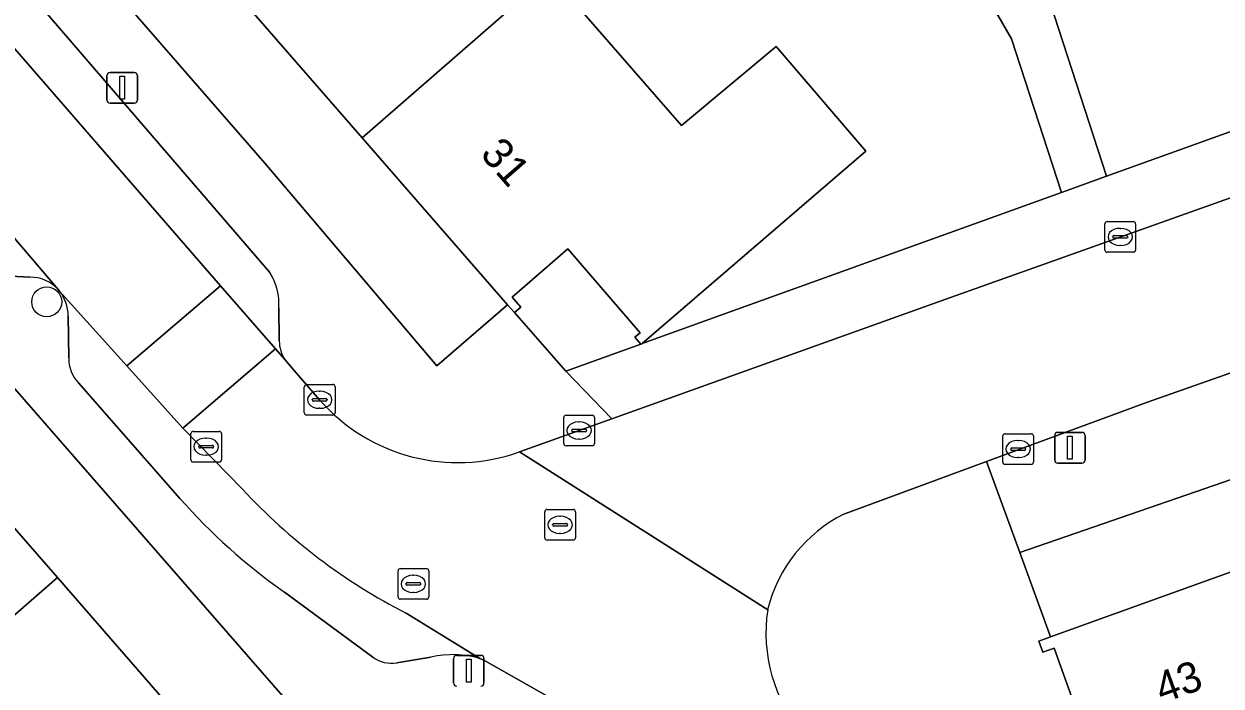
# Model space of a CAD drawing. Extents: x 162523 to 163266, y 381230 to 382050.
# Drawn here: x 162679.21 to 162718.25, y 381760.98 to 381782.56 of the extents above; entities that cross this region are included whole.
import ezdxf

# ---------------------------------------------------------------- set-up
doc = ezdxf.new("R2010")
doc.units = 0
for name, color, linetype in [('IMGEO_Boom', 7, 'Continuous'), ('IMGEO_Erf', 7, 'Continuous'), ('IMGEO_Kolk', 7, 'Continuous'), ('IMGEO_Lichtmast', 7, 'Continuous'), ('IMGEO_Pand', 7, 'Continuous'), ('IMGEO_Pand_nummerreeks', 7, 'Continuous'), ('IMGEO_Parkeervlak_open', 7, 'Continuous'), ('IMGEO_Rijbaan_lokaal_open', 7, 'Continuous'), ('IMGEO_Rioolput', 7, 'Continuous'), ('IMGEO_Voetpad_open', 7, 'Continuous')]:
    doc.layers.add(name, color=color, linetype=linetype)

msp = doc.modelspace()

# ---------------------------------------------------------------- linework, layer by layer
at = {"layer": 'IMGEO_Boom'}
msp.add_circle((162679.951, 381773.503), 0.489, dxfattribs=at)
at = {"layer": 'IMGEO_Erf'}
for points in [[(162646.757, 381824.316), (162687.062, 381778.024), (162692.677, 381771.414), (162694.979, 381773.409), (162690.237, 381778.855), (162685.66, 381784.112), (162681.084, 381789.369), (162676.507, 381794.626), (162671.93, 381799.882), (162667.354, 381805.138), (162662.776, 381810.395), (162658.2, 381815.652), (162653.622, 381820.909), (162648.917, 381826.314)], [(162691.781, 381755.909), (162641.055, 381814.077), (162638.825, 381812.07), (162643.552, 381806.65), (162648.146, 381801.382), (162652.703, 381796.157), (162657.326, 381790.856), (162661.852, 381785.666), (162666.513, 381780.321), (162671.069, 381775.096), (162675.726, 381769.756), (162680.299, 381764.512), (162684.872, 381759.269), (162689.516, 381753.943)], [(162771.368, 381786.733), (162721.003, 381768.545), (162711.69, 381765.328), (162712.683, 381762.58), (162719.702, 381765.1), (162726.218, 381767.44), (162732.846, 381769.821), (162739.192, 381772.1), (162745.775, 381774.464), (162752.294, 381776.805), (162759.028, 381779.223), (162765.611, 381781.587), (162772.373, 381784.016)], [(162699.131, 381772.351), (162699.306, 381772.491), (162696.945, 381775.228), (162695.132, 381773.65), (162695.409, 381773.331), (162695.203, 381773.152), (162696.883, 381771.248), (162699.326, 381772.127)]]:
    msp.add_lwpolyline(points, close=True, dxfattribs=at)
for points in [[(162696.359, 381784.183), (162700.653, 381779.252), (162703.745, 381781.827), (162706.667, 381778.414), (162699.372, 381772.144), (162713.049, 381777.067), (162711.421, 381782.079), (162710.363, 381783.912)], [(162712.395, 381784.129), (162714.518, 381777.596), (162732.297, 381783.996)]]:
    msp.add_lwpolyline(points, dxfattribs=at)
at = {"layer": 'IMGEO_Kolk'}
for p, q in [((162714.538, 381776.119), (162715.39, 381776.119)), ((162714.463, 381775.193), (162714.463, 381776.045)), ((162714.951, 381775.899), (162714.976, 381775.899)), ((162715.464, 381776.045), (162715.464, 381775.193)), ((162714.722, 381775.613), (162714.722, 381775.625)), ((162715.16, 381775.576), (162714.762, 381775.576)), ((162714.765, 381775.662), (162715.163, 381775.662)), ((162714.974, 381775.339), (162714.949, 381775.339)), ((162715.206, 381775.625), (162715.206, 381775.613)), ((162715.39, 381775.119), (162714.538, 381775.119)), ((162688.353, 381769.885), (162688.353, 381770.737)), ((162688.428, 381770.811), (162689.28, 381770.811)), ((162689.354, 381770.737), (162689.354, 381769.885)), ((162688.612, 381770.305), (162688.612, 381770.317)), ((162689.05, 381770.268), (162688.652, 381770.268)), ((162688.655, 381770.354), (162689.053, 381770.354)), ((162688.841, 381770.591), (162688.866, 381770.591)), ((162689.096, 381770.317), (162689.096, 381770.305)), ((162688.864, 381770.031), (162688.839, 381770.031)), ((162689.28, 381769.811), (162688.428, 381769.811)), ((162696.813, 381768.882), (162696.813, 381769.734)), ((162696.888, 381769.808), (162697.74, 381769.808)), ((162697.301, 381769.588), (162697.326, 381769.588)), ((162697.814, 381769.734), (162697.814, 381768.882)), ((162684.652, 381768.355), (162684.652, 381769.207)), ((162684.727, 381769.281), (162685.579, 381769.281)), ((162685.14, 381769.061), (162685.165, 381769.061)), ((162685.653, 381769.207), (162685.653, 381768.355)), ((162697.072, 381769.302), (162697.072, 381769.314)), ((162697.51, 381769.265), (162697.112, 381769.265)), ((162697.115, 381769.351), (162697.513, 381769.351)), ((162697.556, 381769.314), (162697.556, 381769.302)), ((162711.13, 381768.278), (162711.13, 381769.13)), ((162711.205, 381769.204), (162712.057, 381769.204)), ((162712.131, 381769.13), (162712.131, 381768.278)), ((162684.911, 381768.775), (162684.911, 381768.787)), ((162685.349, 381768.738), (162684.951, 381768.738)), ((162684.954, 381768.824), (162685.352, 381768.824)), ((162685.395, 381768.787), (162685.395, 381768.775)), ((162697.74, 381768.808), (162696.888, 381768.808)), ((162697.324, 381769.028), (162697.299, 381769.028)), ((162711.389, 381768.698), (162711.389, 381768.71)), ((162711.432, 381768.747), (162711.83, 381768.747)), ((162711.618, 381768.984), (162711.643, 381768.984)), ((162711.873, 381768.71), (162711.873, 381768.698)), ((162685.579, 381768.281), (162684.727, 381768.281)), ((162685.163, 381768.501), (162685.138, 381768.501)), ((162711.827, 381768.661), (162711.429, 381768.661)), ((162711.641, 381768.424), (162711.616, 381768.424)), ((162712.057, 381768.204), (162711.205, 381768.204))]:
    msp.add_line(p, q, dxfattribs=at)
for points in [[(162714.538, 381776.119), (162715.39, 381776.119)], [(162714.463, 381775.193), (162714.463, 381776.045)], [(162715.464, 381776.045), (162715.464, 381775.193)], [(162715.39, 381775.119), (162714.538, 381775.119)], [(162688.353, 381769.885), (162688.353, 381770.737)], [(162688.428, 381770.811), (162689.28, 381770.811)], [(162689.354, 381770.737), (162689.354, 381769.885)], [(162689.28, 381769.811), (162688.428, 381769.811)], [(162696.813, 381768.882), (162696.813, 381769.734)], [(162696.888, 381769.808), (162697.74, 381769.808)], [(162697.814, 381769.734), (162697.814, 381768.882)], [(162684.652, 381768.355), (162684.652, 381769.207)], [(162684.727, 381769.281), (162685.579, 381769.281)], [(162685.653, 381769.207), (162685.653, 381768.355)], [(162711.13, 381768.278), (162711.13, 381769.13)], [(162711.205, 381769.204), (162712.057, 381769.204)], [(162712.131, 381769.13), (162712.131, 381768.278)], [(162697.74, 381768.808), (162696.888, 381768.808)], [(162685.579, 381768.281), (162684.727, 381768.281)], [(162712.057, 381768.204), (162711.205, 381768.204)]]:
    msp.add_lwpolyline(points, dxfattribs=at)
for centre, radius, start, end in [((162714.54, 381776.043), 0.0765, 91.552, 178.448), ((162714.54, 381776.043), 0.0765, 91.552, 178.448), ((162715.388, 381776.043), 0.0765, 1.552, 88.448), ((162715.388, 381776.043), 0.0765, 1.552, 88.448), ((162714.762, 381775.622), 0.0403, 85.8775, 175.7526), ((162714.759, 381775.612), 0.0366, 178.938, 274.7102), ((162715.163, 381775.619), 0.043, 264.8664, 352.4533), ((162715.167, 381775.624), 0.0386, 1.7309, 96.639), ((162714.54, 381775.195), 0.0765, 181.552, 268.448), ((162714.54, 381775.195), 0.0765, 181.552, 268.448), ((162715.388, 381775.195), 0.0765, 271.552, 358.448), ((162715.388, 381775.195), 0.0765, 271.552, 358.448), ((162688.43, 381770.735), 0.0765, 91.552, 178.448), ((162688.43, 381770.735), 0.0765, 91.552, 178.448), ((162689.278, 381770.735), 0.0765, 1.552, 88.448), ((162689.278, 381770.735), 0.0765, 1.552, 88.448), ((162688.652, 381770.314), 0.0403, 85.8775, 175.7526), ((162688.649, 381770.304), 0.0366, 178.938, 274.7102), ((162689.053, 381770.311), 0.043, 264.8664, 352.4533), ((162689.057, 381770.316), 0.0386, 1.7309, 96.639), ((162688.43, 381769.887), 0.0765, 181.552, 268.448), ((162688.43, 381769.887), 0.0765, 181.552, 268.448), ((162689.278, 381769.887), 0.0765, 271.552, 358.448), ((162689.278, 381769.887), 0.0765, 271.552, 358.448), ((162696.89, 381769.732), 0.0765, 91.552, 178.448), ((162696.89, 381769.732), 0.0765, 91.552, 178.448), ((162697.738, 381769.732), 0.0765, 1.552, 88.448), ((162697.738, 381769.732), 0.0765, 1.552, 88.448), ((162684.729, 381769.205), 0.0765, 91.552, 178.448), ((162684.729, 381769.205), 0.0765, 91.552, 178.448), ((162685.577, 381769.205), 0.0765, 1.552, 88.448), ((162685.577, 381769.205), 0.0765, 1.552, 88.448), ((162697.112, 381769.311), 0.0403, 85.8775, 175.7526), ((162697.109, 381769.301), 0.0366, 178.938, 274.7102), ((162697.513, 381769.308), 0.043, 264.8664, 352.4533), ((162697.517, 381769.313), 0.0386, 1.7309, 96.639), ((162711.207, 381769.128), 0.0765, 91.552, 178.448), ((162711.207, 381769.128), 0.0765, 91.552, 178.448), ((162712.055, 381769.128), 0.0765, 1.552, 88.448), ((162712.055, 381769.128), 0.0765, 1.552, 88.448), ((162684.951, 381768.784), 0.0403, 85.8775, 175.7526), ((162684.948, 381768.774), 0.0366, 178.938, 274.7102), ((162685.352, 381768.781), 0.043, 264.8664, 352.4533), ((162685.356, 381768.786), 0.0386, 1.7309, 96.639), ((162696.89, 381768.884), 0.0765, 181.552, 268.448), ((162696.89, 381768.884), 0.0765, 181.552, 268.448), ((162697.738, 381768.884), 0.0765, 271.552, 358.448), ((162697.738, 381768.884), 0.0765, 271.552, 358.448), ((162711.429, 381768.707), 0.0403, 85.8775, 175.7526), ((162711.426, 381768.697), 0.0366, 178.938, 274.7102), ((162711.83, 381768.704), 0.043, 264.8664, 352.4533), ((162711.834, 381768.709), 0.0386, 1.7309, 96.639), ((162684.729, 381768.357), 0.0765, 181.552, 268.448), ((162684.729, 381768.357), 0.0765, 181.552, 268.448), ((162685.577, 381768.357), 0.0765, 271.552, 358.448), ((162685.577, 381768.357), 0.0765, 271.552, 358.448), ((162711.207, 381768.28), 0.0765, 181.552, 268.448), ((162711.207, 381768.28), 0.0765, 181.552, 268.448), ((162712.055, 381768.28), 0.0765, 271.552, 358.448), ((162712.055, 381768.28), 0.0765, 271.552, 358.448)]:
    msp.add_arc(centre, radius, start, end, dxfattribs=at)
for centre, major_axis, ratio, start_param, end_param in [((162714.95, 381775.619), (-0.387, 0.002), 0.722429, 4.712389, 7.853982), ((162714.975, 381775.619), (-0.39, 0.002), 0.717154, 1.570796, 4.712389), ((162688.84, 381770.311), (-0.387, 0.002), 0.722429, 4.712389, 7.853982), ((162688.865, 381770.311), (-0.39, 0.002), 0.717154, 1.570796, 4.712389), ((162697.3, 381769.308), (-0.387, 0.002), 0.722429, 4.712389, 7.853982), ((162697.325, 381769.308), (-0.39, 0.002), 0.717154, 1.570796, 4.712389), ((162685.139, 381768.781), (-0.387, 0.002), 0.722429, 4.712389, 7.853982), ((162685.164, 381768.781), (-0.39, 0.002), 0.717154, 1.570796, 4.712389), ((162711.617, 381768.704), (-0.387, 0.002), 0.722429, 4.712389, 7.853982), ((162711.642, 381768.704), (-0.39, 0.002), 0.717154, 1.570796, 4.712389)]:
    msp.add_ellipse(centre, major_axis=major_axis, ratio=ratio, start_param=start_param, end_param=end_param, dxfattribs=at)
at = {"layer": 'IMGEO_Lichtmast'}
for p, q in [((162681.917, 381780.081), (162681.917, 381780.881)), ((162681.917, 381780.881), (162681.917, 381780.081)), ((162682.017, 381780.981), (162682.807, 381780.981)), ((162682.807, 381780.981), (162682.017, 381780.981)), ((162682.907, 381780.881), (162682.907, 381780.081)), ((162682.907, 381780.081), (162682.907, 381780.881)), ((162682.807, 381779.981), (162682.017, 381779.981)), ((162682.017, 381779.981), (162682.807, 381779.981)), ((162712.824, 381768.346), (162712.824, 381769.146)), ((162712.824, 381769.146), (162712.824, 381768.346)), ((162712.924, 381769.246), (162713.714, 381769.246)), ((162713.714, 381769.246), (162712.924, 381769.246)), ((162713.814, 381769.146), (162713.814, 381768.346)), ((162713.814, 381768.346), (162713.814, 381769.146)), ((162713.714, 381768.246), (162712.924, 381768.246)), ((162712.924, 381768.246), (162713.714, 381768.246)), ((162693.222, 381761.076), (162693.222, 381761.876)), ((162693.222, 381761.876), (162693.222, 381761.076)), ((162693.322, 381761.976), (162694.112, 381761.976)), ((162694.112, 381761.976), (162693.322, 381761.976)), ((162694.212, 381761.876), (162694.212, 381761.076)), ((162694.212, 381761.076), (162694.212, 381761.876))]:
    msp.add_line(p, q, dxfattribs=at)
for points in [[(162682.337, 381780.856), (162682.487, 381780.856), (162682.487, 381780.106), (162682.337, 381780.106), (162682.337, 381780.856)], [(162713.244, 381769.121), (162713.394, 381769.121), (162713.394, 381768.371), (162713.244, 381768.371), (162713.244, 381769.121)], [(162693.642, 381761.851), (162693.792, 381761.851), (162693.792, 381761.101), (162693.642, 381761.101), (162693.642, 381761.851)]]:
    msp.add_lwpolyline(points, dxfattribs=at)
for centre, start, end in [((162682.017, 381780.881), 90, 180), ((162682.017, 381780.881), 90, 180), ((162682.807, 381780.881), 0, 90), ((162682.807, 381780.881), 360, 90), ((162682.017, 381780.081), 180, 270), ((162682.017, 381780.081), 180, 270), ((162682.807, 381780.081), 270, 0), ((162682.807, 381780.081), 270, 0), ((162712.924, 381769.146), 90, 180), ((162712.924, 381769.146), 90, 180), ((162713.714, 381769.146), 0, 90), ((162713.714, 381769.146), 360, 90), ((162712.924, 381768.346), 180, 270), ((162712.924, 381768.346), 180, 270), ((162713.714, 381768.346), 270, 0), ((162713.714, 381768.346), 270, 0), ((162693.322, 381761.876), 90, 180), ((162693.322, 381761.876), 90, 180), ((162694.112, 381761.876), 0, 90), ((162694.112, 381761.876), 360, 90), ((162693.322, 381761.076), 180, 270), ((162693.322, 381761.076), 180, 270), ((162694.112, 381761.076), 270, 0), ((162694.112, 381761.076), 270, 0)]:
    msp.add_arc(centre, 0.1, start, end, dxfattribs=at)
at = {"layer": 'IMGEO_Pand'}
for points in [[(162691.782, 381789.44), (162685.66, 381784.112), (162690.237, 381778.855), (162696.359, 381784.183)], [(162706.667, 381778.414), (162703.745, 381781.827), (162700.653, 381779.252), (162696.359, 381784.183), (162690.237, 381778.855), (162694.979, 381773.409), (162695.203, 381773.152), (162695.409, 381773.331), (162695.132, 381773.65), (162696.945, 381775.228), (162699.306, 381772.491), (162699.131, 381772.351), (162699.326, 381772.127), (162699.337, 381772.114), (162699.372, 381772.144)], [(162670.965, 381756.372), (162680.299, 381764.512), (162675.726, 381769.756), (162669.657, 381764.465), (162666.565, 381761.768), (162666.392, 381761.617)], [(162722.235, 381757.375), (162719.702, 381765.1), (162712.683, 381762.58), (162712.302, 381762.443), (162712.433, 381762.08), (162712.806, 381762.214), (162715.287, 381755.295), (162714.957, 381755.177), (162715.088, 381754.812), (162715.507, 381754.962), (162719.795, 381756.5)], [(162678.803, 381753.977), (162684.872, 381759.269), (162680.299, 381764.512), (162670.965, 381756.372), (162675.537, 381751.129)]]:
    msp.add_lwpolyline(points, close=True, dxfattribs=at)
at = {"layer": 'IMGEO_Parkeervlak_open'}
for points in [[(162680.341, 381773.889), (162662.382, 381794.94)], [(162675.182, 381786.047), (162685.624, 381774.027), (162687.414, 381771.967), (162687.717, 381771.618)], [(162687.231, 381774.456), (162677.863, 381785.328)], [(162678.333, 381774.357), (162679.399, 381774.307)], [(162686.333, 381767.393), (162684.387, 381769.383), (162682.563, 381771.414), (162680.363, 381773.863)], [(162680.65, 381773.042), (162680.674, 381771.674)], [(162687.534, 381772.229), (162687.525, 381773.31)], [(162680.99, 381770.86), (162684.295, 381767.095)], [(162687.702, 381764.041), (162690.591, 381761.914)], [(162694.08, 381761.879), (162691.678, 381763.348)], [(162691.365, 381761.735), (162692.483, 381761.923)]]:
    msp.add_lwpolyline(points, dxfattribs=at)
for centre, radius, start, end in [((162679.42, 381773.083), 1.224, 41.1812, 90.9616), ((162685.506, 381773.403), 2.021, 357.3675, 31.4097), ((162679.362, 381773.053), 1.288, 359.5322, 39.0044), ((162688.706, 381772.247), 1.172, 180.8814, 212.4655), ((162681.756, 381771.626), 1.083, 177.4331, 225), ((162700.642, 381780.747), 19.573, 223.0226, 242.7418), ((162698.833, 381779.886), 19.364, 221.3423, 234.9123), ((162691.192, 381762.752), 1.031, 234.3252, 279.6315), ((162693.194, 381758.73), 3.271, 74.2875, 102.5561)]:
    msp.add_arc(centre, radius, start, end, dxfattribs=at)
at = {"layer": 'IMGEO_Rijbaan_lokaal_open'}
for points in [[(162657.041, 381806.925), (162656.941, 381807.04), (162648.176, 381817.107), (162645.167, 381814.823), (162645.551, 381814.298), (162645.795, 381814.018), (162645.988, 381813.796), (162650.954, 381808.077), (162662.249, 381795.093), (162662.382, 381794.94), (162680.341, 381773.889), (162680.363, 381773.863), (162682.563, 381771.414), (162685.624, 381774.027), (162675.182, 381786.047), (162675.062, 381786.174)], [(162687.414, 381771.967), (162685.624, 381774.027), (162682.563, 381771.414), (162684.387, 381769.383)]]:
    msp.add_lwpolyline(points, close=True, dxfattribs=at)
for points in [[(162810.992, 381807.398), (162807.475, 381806.37), (162804.287, 381805.438), (162800.354, 381804.283), (162796.87, 381803.259), (162787.905, 381800.573), (162778.822, 381797.969), (162772.588, 381796.113), (162768.08, 381794.68), (162761.762, 381792.555), (162754.947, 381789.947), (162750.568, 381788.41), (162740.129, 381784.59), (162736.996, 381783.467), (162733.281, 381782.136), (162727.293, 381779.975), (162723.508, 381778.659), (162709.271, 381773.592), (162698.385, 381769.691), (162695.37, 381768.61), (162703.464, 381763.466)], [(162705.951, 381766.584), (162710.603, 381768.297), (162715.816, 381770.216), (162727.812, 381774.435), (162743.537, 381780.118), (162755.484, 381784.46), (162766.727, 381788.461), (162769.038, 381789.246), (162772.813, 381790.449), (162776.799, 381791.68), (162781.286, 381793.023), (162787.489, 381794.819), (162796.363, 381797.487)], [(162688.851, 381770.313), (162688.021, 381771.269), (162687.717, 381771.618), (162687.414, 381771.967), (162684.387, 381769.383), (162686.333, 381767.393)], [(162703.464, 381763.466), (162695.37, 381768.61)], [(162691.678, 381763.348), (162694.08, 381761.879), (162694.206, 381761.823), (162698.967, 381759.13)]]:
    msp.add_lwpolyline(points, dxfattribs=at)
for centre, radius, start, end in [((162693.356, 381774.23), 5.97, 221.0047, 289.7142), ((162700.642, 381780.747), 19.573, 223.0226, 242.7418), ((162708.099, 381762.32), 4.775, 116.738, 166.1084), ((162708.5, 381762.706), 5.093, 171.4192, 220.2885)]:
    msp.add_arc(centre, radius, start, end, dxfattribs=at)
at = {"layer": 'IMGEO_Rioolput'}
for p, q in [((162696.268, 381766.734), (162697.12, 381766.734)), ((162696.193, 381765.808), (162696.193, 381766.66)), ((162696.681, 381766.514), (162696.706, 381766.514)), ((162697.194, 381766.66), (162697.194, 381765.808)), ((162696.452, 381766.228), (162696.452, 381766.24)), ((162696.89, 381766.191), (162696.492, 381766.191)), ((162696.495, 381766.277), (162696.893, 381766.277)), ((162696.704, 381765.954), (162696.679, 381765.954)), ((162696.936, 381766.24), (162696.936, 381766.228)), ((162697.12, 381765.734), (162696.268, 381765.734)), ((162691.483, 381764.808), (162692.335, 381764.808)), ((162691.408, 381763.882), (162691.408, 381764.734)), ((162691.896, 381764.588), (162691.921, 381764.588)), ((162692.409, 381764.734), (162692.409, 381763.882)), ((162691.667, 381764.302), (162691.667, 381764.314)), ((162692.105, 381764.265), (162691.707, 381764.265)), ((162691.71, 381764.351), (162692.108, 381764.351)), ((162691.919, 381764.028), (162691.894, 381764.028)), ((162692.151, 381764.314), (162692.151, 381764.302)), ((162692.335, 381763.808), (162691.483, 381763.808))]:
    msp.add_line(p, q, dxfattribs=at)
for points in [[(162696.268, 381766.734), (162697.12, 381766.734)], [(162696.193, 381765.808), (162696.193, 381766.66)], [(162697.194, 381766.66), (162697.194, 381765.808)], [(162697.12, 381765.734), (162696.268, 381765.734)], [(162691.483, 381764.808), (162692.335, 381764.808)], [(162691.408, 381763.882), (162691.408, 381764.734)], [(162692.409, 381764.734), (162692.409, 381763.882)], [(162692.335, 381763.808), (162691.483, 381763.808)]]:
    msp.add_lwpolyline(points, dxfattribs=at)
for centre, radius, start, end in [((162696.27, 381766.658), 0.0765, 91.552, 178.448), ((162696.27, 381766.658), 0.0765, 91.552, 178.448), ((162697.118, 381766.658), 0.0765, 1.552, 88.448), ((162697.118, 381766.658), 0.0765, 1.552, 88.448), ((162696.492, 381766.237), 0.0403, 85.8775, 175.7526), ((162696.489, 381766.227), 0.0366, 178.938, 274.7102), ((162696.893, 381766.234), 0.043, 264.8664, 352.4533), ((162696.897, 381766.239), 0.0386, 1.7309, 96.639), ((162696.27, 381765.81), 0.0765, 181.552, 268.448), ((162696.27, 381765.81), 0.0765, 181.552, 268.448), ((162697.118, 381765.81), 0.0765, 271.552, 358.448), ((162697.118, 381765.81), 0.0765, 271.552, 358.448), ((162691.485, 381764.732), 0.0765, 91.552, 178.448), ((162691.485, 381764.732), 0.0765, 91.552, 178.448), ((162692.333, 381764.732), 0.0765, 1.552, 88.448), ((162692.333, 381764.732), 0.0765, 1.552, 88.448), ((162691.707, 381764.311), 0.0403, 85.8775, 175.7526), ((162691.704, 381764.301), 0.0366, 178.938, 274.7102), ((162692.108, 381764.308), 0.043, 264.8664, 352.4533), ((162692.112, 381764.313), 0.0386, 1.7309, 96.639), ((162691.485, 381763.884), 0.0765, 181.552, 268.448), ((162691.485, 381763.884), 0.0765, 181.552, 268.448), ((162692.333, 381763.884), 0.0765, 271.552, 358.448), ((162692.333, 381763.884), 0.0765, 271.552, 358.448)]:
    msp.add_arc(centre, radius, start, end, dxfattribs=at)
for centre, major_axis, ratio, start_param, end_param in [((162696.68, 381766.234), (-0.387, 0.002), 0.722429, 4.712389, 7.853982), ((162696.705, 381766.234), (-0.39, 0.002), 0.717154, 1.570796, 4.712389), ((162691.895, 381764.308), (-0.387, 0.002), 0.722429, 4.712389, 7.853982), ((162691.92, 381764.308), (-0.39, 0.002), 0.717154, 1.570796, 4.712389)]:
    msp.add_ellipse(centre, major_axis=major_axis, ratio=ratio, start_param=start_param, end_param=end_param, dxfattribs=at)
at = {"layer": 'IMGEO_Voetpad_open'}
for points in [[(162695.37, 381768.61), (162698.385, 381769.691), (162696.883, 381771.248), (162695.203, 381773.152), (162694.979, 381773.409), (162692.677, 381771.414), (162687.062, 381778.024), (162646.757, 381824.316)], [(162641.055, 381814.077), (162691.781, 381755.909), (162689.516, 381753.943), (162689.875, 381753.532), (162690.707, 381752.54), (162694.637, 381755.807), (162694.344, 381756.159), (162694.627, 381756.394), (162694.953, 381756.002), (162696.544, 381757.406)], [(162819.812, 381804.396), (162808.82, 381801.17), (162802.377, 381799.307), (162796.363, 381797.487), (162787.489, 381794.819), (162781.286, 381793.023), (162776.799, 381791.68), (162772.813, 381790.449), (162769.038, 381789.246), (162766.727, 381788.461), (162755.484, 381784.46), (162743.537, 381780.118), (162727.812, 381774.435), (162715.816, 381770.216), (162710.603, 381768.297), (162711.69, 381765.328), (162721.003, 381768.545), (162771.368, 381786.733), (162772.373, 381784.016), (162772.781, 381784.162), (162774.9, 381784.789), (162775.329, 381784.916), (162774.54, 381787.759), (162837.328, 381806.26)], [(162675.808, 381785.84), (162677.178, 381785.697), (162677.863, 381785.328), (162687.231, 381774.456)], [(162732.297, 381783.996), (162714.518, 381777.596), (162713.049, 381777.067), (162699.372, 381772.144), (162699.337, 381772.114), (162699.326, 381772.127), (162696.883, 381771.248), (162698.385, 381769.691), (162709.271, 381773.592), (162723.508, 381778.659)], [(162710.363, 381783.912), (162711.421, 381782.079), (162713.049, 381777.067), (162714.518, 381777.596), (162712.395, 381784.129)], [(162679.399, 381774.307), (162678.333, 381774.357)], [(162680.363, 381773.863), (162680.341, 381773.889)], [(162680.674, 381771.674), (162680.65, 381773.042)], [(162687.525, 381773.31), (162687.534, 381772.229)], [(162687.717, 381771.618), (162688.021, 381771.269), (162688.851, 381770.313)], [(162684.295, 381767.095), (162680.99, 381770.86)], [(162712.806, 381762.214), (162712.433, 381762.08), (162712.302, 381762.443), (162712.683, 381762.58), (162711.69, 381765.328), (162710.603, 381768.297), (162705.951, 381766.584)], [(162690.591, 381761.914), (162687.702, 381764.041)], [(162726.488, 381738.887), (162724.481, 381741.349), (162724.241, 381741.622), (162723.467, 381742.504), (162723.333, 381742.657), (162721.308, 381745.14), (162718.054, 381750), (162716.34, 381752.561), (162715.507, 381754.962), (162715.088, 381754.812), (162714.957, 381755.177), (162715.287, 381755.295), (162712.806, 381762.214)], [(162692.483, 381761.923), (162691.365, 381761.735)], [(162698.967, 381759.13), (162694.206, 381761.823), (162694.08, 381761.879)]]:
    msp.add_lwpolyline(points, dxfattribs=at)
for centre, radius, start, end in [((162679.42, 381773.083), 1.224, 41.1812, 90.9616), ((162685.506, 381773.403), 2.021, 357.3675, 31.4097), ((162679.362, 381773.053), 1.288, 359.5322, 39.0044), ((162688.706, 381772.247), 1.172, 180.8814, 212.4655), ((162681.756, 381771.626), 1.083, 177.4331, 225), ((162693.356, 381774.23), 5.97, 221.0047, 289.7142), ((162698.833, 381779.886), 19.364, 221.3423, 234.9123), ((162708.099, 381762.32), 4.775, 116.738, 166.1084), ((162708.5, 381762.706), 5.093, 171.4192, 220.2885), ((162691.192, 381762.752), 1.031, 234.3252, 279.6315), ((162693.194, 381758.73), 3.271, 74.2875, 102.5561)]:
    msp.add_arc(centre, radius, start, end, dxfattribs=at)

# ---------------------------------------------------------------- texts
at = {"layer": 'IMGEO_Pand_nummerreeks'}
for s, rotation, p in [('31', 311.0448, (162694.058, 381778.304)), ('43', 19.754, (162716.322, 381760.402))]:
    msp.add_text(s, height=1, rotation=rotation, dxfattribs=at).set_placement(p)

doc.saveas('drawing.dxf')
